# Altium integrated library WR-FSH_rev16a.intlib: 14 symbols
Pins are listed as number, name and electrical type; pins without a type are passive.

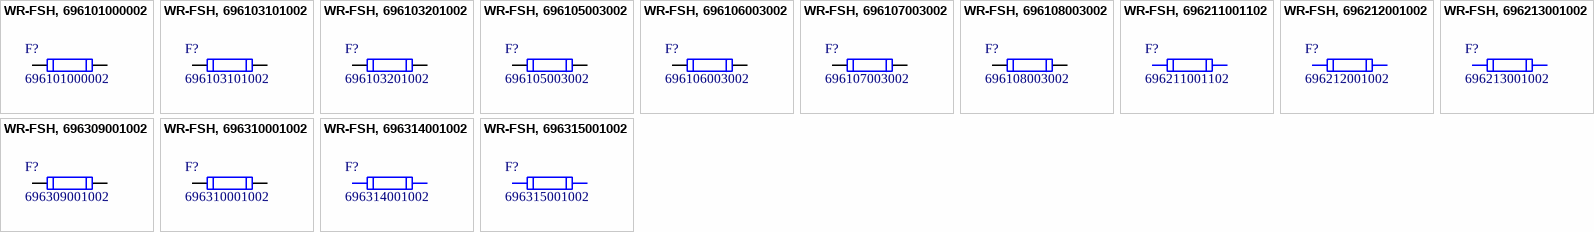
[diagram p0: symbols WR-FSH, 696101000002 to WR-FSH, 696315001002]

## WR-FSH, 696101000002
designator F?, comment 696101000002
WR-FSH Fuseholder THT Blocks PCB Clip Cover; Manufacturer: Wurth Elektronik; ComponentLink1 Description: Manufacturer; ComponentLink2 Description: Datasheet; NoPins: 2
footprint 696101000002 (FUSEHOLDER BLOCKS - PCB - CLIP COVER - THT - WR-FSH)
pins: 1, 2

## WR-FSH, 696103101002
designator F?, comment 696103101002
WR-FSH Fuseholder SMT Blocks PCB Clip Cover; Manufacturer: Wurth Elektronik; ComponentLink1 Description: Manufacturer; ComponentLink2 Description: Datasheet; NoPins: 2
footprint 696103101002 (PCB - Clip Cover - SMT)
pins: 1, 2

## WR-FSH, 696103201002
designator F?, comment 696103201002
WR-FSH Fuseholder THR Blocks PCB Clip Cover; Manufacturer: Wurth Elektronik; ComponentLink1 Description: Manufacturer; ComponentLink2 Description: Datasheet; NoPins: 2
footprint 696103201002 (PCB - Clip Cover - THR)
pins: 1, 2

## WR-FSH, 696105003002
designator F?, comment 696105003002
WR-FSH Fuseholder THT Blocks PCB Clip Cover; Manufacturer: Wurth Elektronik; ComponentLink1 Description: Manufacturer; ComponentLink2 Description: Datasheet; NoPins: 2
footprint 696105003002 (FUSEHOLDER BLOCKS - PCB - CLIP COVER - THT - WR-FSH)
pins: 1, 2

## WR-FSH, 696106003002
designator F?, comment 696106003002
WR-FSH Fuseholder THT Blocks PCB Clip Cover; Manufacturer: Wurth Elektronik; ComponentLink1 Description: Manufacturer; ComponentLink2 Description: Datasheet; NoPins: 2
footprint 696106003002 (FUSEHOLDER BLOCKS - PCB - CLIP COVER - THT - WR-FSH)
pins: 1, 2

## WR-FSH, 696107003002
designator F?, comment 696107003002
WR-FSH Fuseholder THT Blocks PCB Clip Cover; Manufacturer: Wurth Elektronik; ComponentLink1 Description: Manufacturer; ComponentLink2 Description: Datasheet; NoPins: 2
footprint 696107003002 (FUSEHOLDER BLOCKS - PCB - CLIP COVER - THT - WR-FSH)
pins: 1, 2

## WR-FSH, 696108003002
designator F?, comment 696108003002
WR-FSH Fuseholder THT Blocks PCB Clip Cover; Manufacturer: Wurth Elektronik; ComponentLink1 Description: Manufacturer; ComponentLink2 Description: Datasheet; NoPins: 2
footprint 696108003002 (FUSEHOLDER BLOCKS - PCB - CLIP COVER - THT - WR-FSH)
pins: 1, 2

## WR-FSH, 696211001102
designator F?, comment 696211001102
WR-FSH Shocksafe Fuseholder-Panel-Screw and Lock Cover-THT-Glow wire Plastic; Manufacturer: Wurth Elektronik; ComponentLink1 Description: Manufacturer; ComponentLink2 Description: Datasheet
footprint 696211001102 (WR-FSH Shocksafe Fuseholder-Panel-Screw and Lock Cover-THT-Glow wire Plastic)

## WR-FSH, 696212001002
designator F?, comment 696212001002
WR-FSH Shocksafe Fuseholder-Panel-Screw and Lock Cover-THT; Manufacturer: Wurth Elektronik; ComponentLink1 Description: Manufacturer; ComponentLink2 Description: Datasheet
footprint 696212001002 (WR-FSH Shocksafe Fuseholder-Panel-Screw and Lock Cover-THT)

## WR-FSH, 696213001002
designator F?, comment 696213001002
WR-FSH Shocksafe Fuseholder-Panel-Screw and Lock Cover-THT; Manufacturer: Wurth Elektronik; ComponentLink1 Description: Manufacturer; ComponentLink2 Description: Datasheet
footprint 696213001002 (WR-FSH Shocksafe Fuseholder-Panel-Screw and Lock Cover-THT)

## WR-FSH, 696309001002
designator F?, comment 696309001002
WR-FSH Shocksafe Fuseholder-PCB-Turn and Lock Cover-THT; Manufacturer: Wurth Elektronik; ComponentLink1 Description: Manufacturer; ComponentLink2 Description: Datasheet; NoPins: 2
footprint 696309001002 (WR-FSH Shocksafe Fuseholder-PCB-Turn and Lock Cover-THT)
pins: 1, 2

## WR-FSH, 696310001002
designator F?, comment 696310001002
WR-FSH Shocksafe Fuseholder-PCB-Turn and Lock Cover-THT; Manufacturer: Würth Elektronik eiSos GmbH; ComponentLink1 Description: Manufacturer; ComponentLink2 Description: Datasheet; NoPins: 2
footprint 696310001002 (WR-FSH Shocksafe Fuseholder-PCB-Turn and Lock Cover-THT)
pins: 1, 2

## WR-FSH, 696314001002
designator F?, comment 696314001002
WR-FSH Shocksafe Fuseholder-Panel-Turn and Lock Cover-THT; Manufacturer: Wurth Elektronik; ComponentLink1 Description: Manufacturer; ComponentLink2 Description: Datasheet
footprint 696314001002 (WR-FSH Shocksafe Fuseholder-Panel-Turn and Lock Cover-THT)

## WR-FSH, 696315001002
designator F?, comment 696315001002
WR-FSH Shocksafe Fuseholder-Panel-Turn and Lock Cover-THT; Manufacturer: Wurth Elektronik; ComponentLink1 Description: Manufacturer; ComponentLink2 Description: Datasheet
footprint 696315001002 (WR-FSH Shocksafe Fuseholder-Panel-Turn and Lock Cover-THT)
